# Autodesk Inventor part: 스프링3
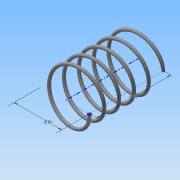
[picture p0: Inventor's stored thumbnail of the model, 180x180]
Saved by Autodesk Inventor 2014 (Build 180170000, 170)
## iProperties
Created: 2015-06
Part Number: 스프링3
Material: 강철, 연강
Document SubType Name: Modeling
Designer: MYHOME
Density: 7.86 g/cm^3
Appearance: 강철
Mass: 1.53479 g
Surface Area: 7.89194 cm^2
Volume: 0.195266 cm^3
Author: MYHOME
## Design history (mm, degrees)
sketch "스케치1"
  geometry: L1 (0, 0)-(8, 0); L2 (8, 0)-(8, 21.5); L3 (8, 21.5)-(0, 21.5); L4 (0, 21.5)-(0, 0); C1 r 0.5 at (8, 0)
  constraints: 8 end point, 2 parallel, 1 centre point, 1 coincident, 1 horizontal, 1 perpendicular
  dimensions: "d0" = 16 diameter of L2 L4; "d1" = 21.5 distance of L1.end L2.end (derived); "d2" = 1 diameter of C1
feature "코일2" sketch "스케치1" pitch "d17" = 10; turns "d19" = 5; dims "d18" = 21.5 (= d1), "d20" = 0, angle "d21" = 90 deg, angle "d22" = 90 deg, "d23" = 0, "d24" = 0
node "작업 평면3"
sketch "스케치4"
  geometry: L1 (-8.5, 0)-(-7.5, 0) reference; 1 further point
  constraints: 1 horizontal alignment
extrude "돌출3" cut sketch "스케치4" stored distance "d26" = 10; taper "d27" = 0 deg
node "작업 평면4"
sketch "스케치5"
  geometry: L1 (-7.5, 0)-(-8.5, 0) reference; 1 further point
  constraints: 1 horizontal alignment
extrude "돌출4" cut sketch "스케치5" stored distance "d29" = 10; taper "d30" = 0 deg
node "솔리드2"
node "절단 모서리 투영3"
node "절단 모서리 투영4"
other parameters: "d25" = 0, "d28" = 21.5 (= d1)
